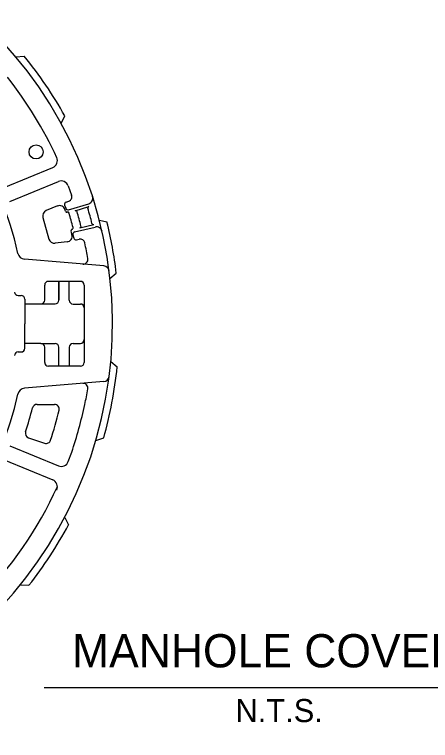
# Model space of a CAD drawing. Extents: x -7.1 to 10, y -5 to 6.
# Drawn here: x -3.691 to -2.543, y -0.43 to 1.576 of the extents above; entities that cross this region are included whole.
import ezdxf

# ---------------------------------------------------------------- set-up
doc = ezdxf.new("R2010")
doc.units = 0
for name, color, linetype in [('Level 1', 7, 'Continuous'), ('Level 12', 7, 'Continuous'), ('Level 14', 7, 'Continuous')]:
    doc.layers.add(name, color=color, linetype=linetype)

msp = doc.modelspace()

# ---------------------------------------------------------------- linework, layer by layer
at = {"layer": 'Level 1'}
for p, q in [((-3.6879, 1.4591), (-3.6646, 1.4609)), ((-3.5625, 1.2751), (-3.5523, 1.296)), ((-3.7202, 1.0978), (-3.5858, 1.1533)), ((-3.7042, 1.0593), (-3.5703, 1.1147)), ((-3.5428, 1.1026), (-3.5336, 1.077)), ((-3.5728, 1.0471), (-3.6041, 1.0342)), ((-3.553, 1.0497), (-3.5501, 1.0407)), ((-3.5488, 1.0579), (-3.5417, 1.0602)), ((-3.542, 1.0365), (-3.4863, 1.0535)), ((-3.5236, 1.0339), (-3.4862, 1.0453)), ((-3.5456, 1.0302), (-3.5458, 1.0301)), ((-3.6132, 1.0155), (-3.5962, 0.9556)), ((-3.4571, 1.0079), (-3.4361, 1.0032)), ((-3.5253, 0.9753), (-3.4686, 0.989)), ((-3.5107, 0.9869), (-3.4727, 0.9961)), ((-3.5356, 0.9778), (-3.5327, 0.9671)), ((-3.5326, 0.9827), (-3.5329, 0.9826)), ((-3.5301, 0.9675), (-3.528, 0.9586)), ((-3.5462, 0.948), (-3.5795, 0.9444)), ((-3.5203, 0.9537), (-3.5127, 0.9553)), ((-3.4446, 0.8817), (-3.6634, 0.8999)), ((-3.4277, 0.8465), (-3.4103, 0.8619)), ((-3.6081, 0.7869), (-3.6081, 0.8285)), ((-3.5977, 0.839), (-3.5091, 0.839)), ((-3.5687, 0.839), (-3.5687, 0.839)), ((-3.5687, 0.839), (-3.5687, 0.7869)), ((-3.5687, 0.7869), (-3.5687, 0.839)), ((-3.5401, 0.7866), (-3.5401, 0.839)), ((-3.4987, 0.8285), (-3.4987, 0.615)), ((-3.681, 0.7998), (-3.6732, 0.7998)), ((-3.6628, 0.7894), (-3.6628, 0.7218)), ((-3.6628, 0.7765), (-3.6185, 0.7765)), ((-3.6185, 0.7765), (-3.5791, 0.7765)), ((-3.5297, 0.7762), (-3.5091, 0.7762)), ((-3.4987, 0.7658), (-3.4987, 0.6778)), ((-3.6628, 0.6541), (-3.6628, 0.7218)), ((-3.6185, 0.6671), (-3.6628, 0.6671)), ((-3.6185, 0.6671), (-3.5791, 0.6671)), ((-3.5297, 0.6674), (-3.5091, 0.6674)), ((-3.681, 0.6437), (-3.6732, 0.6437)), ((-3.6081, 0.615), (-3.6081, 0.6567)), ((-3.5687, 0.6046), (-3.5687, 0.6567)), ((-3.5401, 0.6569), (-3.5401, 0.6046)), ((-3.5091, 0.6046), (-3.5977, 0.6046)), ((-3.4256, 0.6176), (-3.4079, 0.6024)), ((-3.4446, 0.5619), (-3.6634, 0.5437)), ((-3.6292, 0.4989), (-3.581, 0.4989)), ((-3.6526, 0.4067), (-3.6083, 0.3916)), ((-3.4671, 0.3989), (-3.4451, 0.4064)), ((-3.7042, 0.3843), (-3.5703, 0.329)), ((-3.5428, 0.341), (-3.5335, 0.3666)), ((-3.7202, 0.3458), (-3.5858, 0.2903)), ((-3.5527, 0.1867), (-3.5422, 0.1658)), ((-3.6748, 0.0004), (-3.6516, -0.001))]:
    msp.add_line(p, q, dxfattribs=at)
msp.add_circle((-3.6319, 1.1965), 0.0195, dxfattribs=at)
for centre, radius, start, end in [((-4.5726, 0.7218), 1.1516, 195.0717, 189.1227), ((-4.5725, 0.7218), 0.9115, 12.3185, 171.9696), ((-4.5724, 0.7224), 1.1703, 29.3462, 39.1251), ((-4.5725, 0.7217), 1.0983, 24.6593, 38.3184), ((-3.5938, 1.1726), 0.0208, 292.4638, 24.745), ((-3.5624, 1.0954), 0.0208, 20.2003, 112.4638), ((-3.5458, 1.0726), 0.013, 288.1934, 19.9094), ((-3.4908, 1.0684), 0.0156, 286.9986, 17.7663), ((-3.5669, 1.0326), 0.0156, 17.3105, 112.3844), ((-3.5468, 1.0517), 0.00651, 108.1934, 197.8345), ((-3.4851, 1.0416), 0.00391, 106.9986, 196.3936), ((-3.5981, 1.0198), 0.0156, 112.3844, 195.8113), ((-4.5744, 0.7186), 1.071, 17.0555, 17.3105), ((-3.5468, 1.0339), 0.00391, 197.0555, 285.4543), ((-3.5439, 1.0427), 0.00651, 197.3315, 286.9986), ((-3.5446, 1.0264), 0.00391, 16.639, 105.4543), ((-4.5744, 0.7186), 1.0788, 14.4312, 16.639), ((-3.5224, 1.0302), 0.00391, 16.372, 106.9986), ((-4.5725, 0.7217), 1.0983, 14.2261, 16.372), ((-4.5725, 0.7217), 1.1296, 14.2055, 16.3936), ((-4.5722, 0.7224), 1.1703, 6.8462, 13.8863), ((-3.5335, 0.9865), 0.00391, 282.2806, 14.4312), ((-3.5116, 0.9907), 0.00391, 283.6273, 14.2261), ((-3.4737, 0.9999), 0.00391, 194.2055, 283.6273), ((-3.465, 0.9738), 0.0156, 12.8176, 103.6273), ((-3.5479, 0.9635), 0.0156, 276.1827, 13.4177), ((-3.5318, 0.9788), 0.00391, 105.802, 195.2366), ((-3.5237, 0.969), 0.00651, 103.6273, 193.2662), ((-3.5812, 0.9599), 0.0156, 195.8113, 276.1827), ((-3.5217, 0.96), 0.00651, 192.7781, 282.4473), ((-3.5099, 0.9426), 0.013, 11.7446, 102.4473), ((-4.5725, 0.7217), 1.0983, 9.4311, 11.7446), ((-3.6617, 0.9207), 0.0208, 192.3185, 265.2428), ((-3.5018, 0.8995), 0.013, 265.2428, 9.4311), ((-3.4459, 0.8661), 0.0156, 7.299, 85.2428), ((-3.5977, 0.8285), 0.0104, 90, 180), ((-3.5091, 0.8285), 0.0104, 0, 90), ((-3.681, 0.8102), 0.0104, 185.6674, 270), ((-3.6732, 0.7894), 0.0104, 0, 90), ((-3.6185, 0.7869), 0.0104, 270, 0), ((-3.5791, 0.7869), 0.0104, 270, 0), ((-3.5297, 0.7866), 0.0104, 180, 270), ((-3.5091, 0.7658), 0.0104, 0, 90), ((-3.6185, 0.6567), 0.0104, 0, 90), ((-3.5791, 0.6567), 0.0104, 0, 90), ((-3.5297, 0.6569), 0.0104, 90, 180), ((-3.5091, 0.6778), 0.0104, 270, 0), ((-3.681, 0.6333), 0.0104, 90, 174.3326), ((-3.6732, 0.6541), 0.0104, 270, 0), ((-3.5977, 0.615), 0.0104, 180, 270), ((-3.5091, 0.615), 0.0104, 270, 0), ((-4.572, 0.7222), 1.1703, 344.3462, 354.1251), ((-4.5725, 0.7218), 0.9115, 188.0305, 347.6848), ((-3.4459, 0.5775), 0.0156, 274.7589, 352.7027), ((-3.6617, 0.5229), 0.0208, 94.7589, 167.6848), ((-3.5018, 0.5441), 0.013, 350.5705, 94.7589), ((-4.5725, 0.7219), 1.0983, 348.257, 350.5705), ((-4.572, 0.7207), 0.9586, 341.9169, 346.0155), ((-3.6292, 0.4859), 0.013, 90, 166.0155), ((-4.5729, 0.7213), 1.0325, 341.862, 346.6473), ((-3.581, 0.4859), 0.013, 346.6473, 90), ((-4.572, 0.7207), 1.0972, 341.1743, 348.3154), ((-3.6484, 0.4191), 0.013, 161.9169, 251.149), ((-3.6041, 0.4039), 0.013, 251.149, 341.862), ((-3.5624, 0.3482), 0.0208, 247.5378, 339.8014), ((-3.5938, 0.271), 0.0208, 335.2566, 67.5378), ((-4.573, 0.7263), 1.0983, 315.3646, 335.5685), ((-4.5719, 0.722), 1.1703, 321.8462, 331.6251)]:
    msp.add_arc(centre, radius, start, end, dxfattribs=at)
at = {"layer": 'Level 12'}
msp.add_line((-3.6091, -0.2838), (-2.2967, -0.2838), dxfattribs=at)

# ---------------------------------------------------------------- texts
msp.add_text('MANHOLE COVERS', height=0.091813, dxfattribs=at).set_placement((-3.5324, -0.2278))
at = {"layer": 'Level 14'}
msp.add_text('N.T.S.', height=0.06376, dxfattribs=at).set_placement((-3.0813, -0.379))

doc.saveas('drawing.dxf')
